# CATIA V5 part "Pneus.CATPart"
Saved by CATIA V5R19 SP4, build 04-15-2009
Part number: Pneus
Bounding box of the stored display mesh (mm): x -725.841 to 573.841, y -279.239 to 279.239, z -279.239 to 279.239
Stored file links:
  G:\EU_thinkMotion\CFAO_2010\MMS_groupe1\MMS_groupe1\OK\rragonneau\rragonneau\Pneus.CATPart
  F:\Squelette\Deambulateur.CATProduct
  G:\EU_thinkMotion\CFAO_2010\MMS_groupe1\MMS_groupe1\OK\rragonneau\rragonneau\Jante 1.CATPart
  G:\EU_thinkMotion\CFAO_2010\MMS_groupe1\MMS_groupe1\OK\rragonneau\rragonneau\squelette bras 1.CATPart
  G:\EU_thinkMotion\CFAO_2010\MMS_groupe1\MMS_groupe1\OK\rragonneau\rragonneau\squelette de base.CATPart
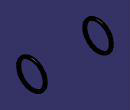
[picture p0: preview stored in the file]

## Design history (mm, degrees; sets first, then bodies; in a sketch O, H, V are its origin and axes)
External parameters (linked from other documents)
  External.epaisseur_pneu = 60 mm
  External.diam_jante = 500 mm
Set1
  Sketch1 on Plane1, origin (0, 0, 0), H (-1, 0, 0), V (0, 0.7705, -0.6374)
    arc A1 centre (-544, 250) radius 30 from (-550, 279.3939) to (-569.9808, 235) ccw
    point P1 (-544, 250)
    point P2 (-550, 279.3939)
    point P3 (-569.9808, 235)
    line L1 (-550, 279.3939) -> (-544, 274)
    point P4 (-544, 274)
    axis line L2 (-544, 382.664) -> (-544, 287.7898)
    line L3 (-569.9808, 235) -> (-544, 235)
    point P7 (-544, 235)
    point P8 (-544, 274)
    point P9 (-538, 279.3939)
    line L4 (-538, 279.3939) -> (-544, 274)
    point P10 (-518.0192, 235)
    point P11 (-538, 279.3939)
    point P12 (-544, 250)
    arc A2 centre (-544, 250) radius 30 from (-538, 279.3939) to (-518.0192, 235) cw
    point P13 (-544, 235)
    point P14 (-518.0192, 235)
    line L5 (-518.0192, 235) -> (-544, 235)
    reference intersected line E1 through (-544, 0) direction (0, -1) from Plane2
    reference projected line E2 (-650, 0) -> (-850, 0) from Line1
    reference intersected line E3 through (-544, 0) direction (0, -1) from Plane2
    distance P1 L3 = 15 {= External.epaisseur_pneu /4}
    radius A1 = 30 {= External.epaisseur_pneu /2}
    distance P4 P1 = 24 {= External.epaisseur_pneu *4/10}
    distance P2 L2 = 6 {= External.epaisseur_pneu *1/10}
    distance E2 P12 = 250 {= External.diam_jante /2}
    vertical: L2 V
    coincidence: P1 L2, P4 L2, P7 L2, L2 E1, P4 P8, P7 P13, P9 P11, P10 P14, L2 E3
    horizontal: L3 H
    symmetry: P4 P8 L2, P2 P9 L2, L1 L4 L2, P3 P10 L2, P2 P11 L2, A1 A2 L2, P7 P13 L2, P3 P14 L2, L3 L5 L2
Set2
  Plane1: linked copy from another document
  Plane2: linked copy from another document
  Line1: linked copy from another document
  Plane3: linked copy from another document
Body1 (main body)
  Shaft1: profile Sketch1, axis Line1, angle 360
  Mirror1: of the body so far, about Plane3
